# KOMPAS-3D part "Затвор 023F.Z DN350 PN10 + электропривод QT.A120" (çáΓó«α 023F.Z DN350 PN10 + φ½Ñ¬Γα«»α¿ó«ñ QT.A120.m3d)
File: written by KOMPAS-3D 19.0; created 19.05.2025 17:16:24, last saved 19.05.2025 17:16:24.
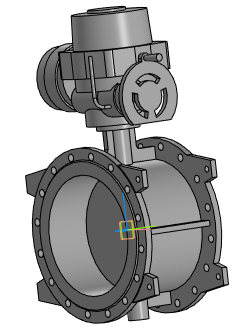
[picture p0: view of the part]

Document properties: Полное имя файла: Затвор 023F.Z DN350 PN10 + электропривод QT.A120.a3d

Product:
- Part/product: Затвор 023F.Z DN350 PN10 + электропривод QT.A120
    Масса: 251.509

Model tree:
1. Операция без истории:1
